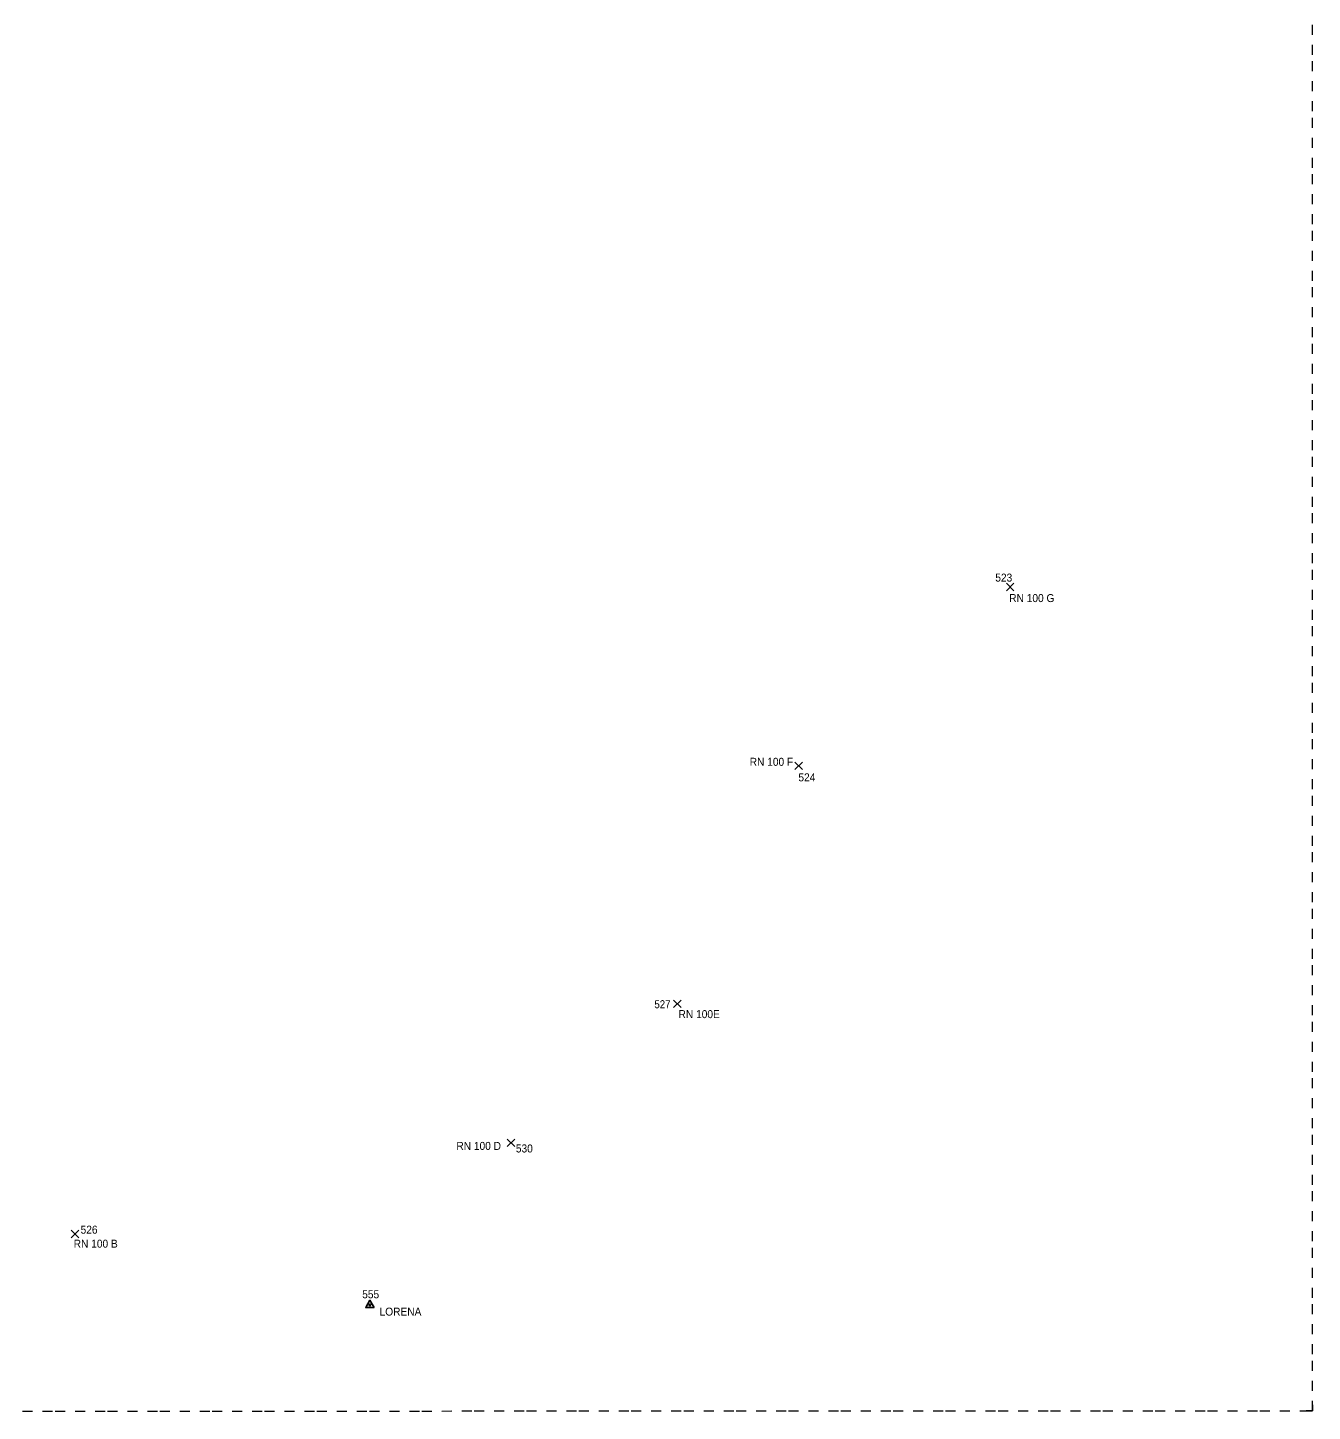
# Model space of a CAD drawing. Extents: x 474.3 to 500, y 7484.1 to 7511.8.
# Drawn here: x 487.15 to 500, y 7484.12 to 7497.95 of the extents above; entities that cross this region are included whole.
import ezdxf
from ezdxf.enums import TextEntityAlignment as Align

# ---------------------------------------------------------------- set-up
doc = ezdxf.new("R2010")
doc.units = 0
doc.header["$LTSCALE"] = 0.032
doc.header["$PDMODE"] = 32
doc.header["$PDSIZE"] = 0.016
doc.linetypes.add('SHORT_DASHED', pattern=[2.7, 1.5, -1.2])
for name, color, linetype, lineweight in [('1', 7, 'SHORT_DASHED', 13), ('42', 7, 'Continuous', 25), ('46', 7, 'Continuous', 25), ('63', 7, 'Continuous', 25)]:
    doc.layers.add(name, color=color, linetype=linetype, lineweight=lineweight)
doc.layers.add('61', color=7, linetype='Continuous')

msp = doc.modelspace()

# ---------------------------------------------------------------- linework, layer by layer
at = {"layer": '1'}
for points in [[(500, 7484.1219), (500, 7484.6867), (500, 7485.2515), (500, 7485.8162), (500, 7486.381), (500, 7486.9458), (500, 7487.5106), (500, 7488.0754), (500, 7488.6402), (500, 7489.2049), (500, 7489.7697), (500, 7490.3345), (500, 7490.8993), (500, 7491.4641), (500, 7492.0289), (500, 7492.5936), (500, 7493.1584), (500, 7493.7232), (500, 7494.288), (500, 7494.8528), (500, 7495.4175), (500, 7495.9823), (500, 7496.5471), (500, 7497.1119), (500, 7497.6767), (500, 7498.2414)], [(486.9038, 7484.1162), (487.4277, 7484.1167), (487.9515, 7484.1171), (488.4754, 7484.1175), (488.9992, 7484.1179), (489.5231, 7484.1183), (490.0469, 7484.1186), (490.5707, 7484.119), (491.0946, 7484.1193), (491.6184, 7484.1196), (492.1423, 7484.1199), (492.6661, 7484.1201), (493.19, 7484.1204), (493.7138, 7484.1206), (494.2377, 7484.1208), (494.7615, 7484.121), (495.2853, 7484.1212), (495.8092, 7484.1213), (496.333, 7484.1214), (496.8569, 7484.1216), (497.3807, 7484.1217), (497.9046, 7484.1217), (498.4284, 7484.1218), (498.9523, 7484.1219), (499.4761, 7484.1219), (500, 7484.1219)]]:
    msp.add_lwpolyline(points, dxfattribs=at)
at = {"layer": '42'}
for p, q in [((496.9411, 7492.394), (497.0161, 7492.319)), ((497.0161, 7492.394), (496.9411, 7492.319)), ((494.8268, 7490.607), (494.9018, 7490.532)), ((494.9018, 7490.607), (494.8268, 7490.532)), ((493.6134, 7488.2272), (493.6884, 7488.1522)), ((493.6884, 7488.2272), (493.6134, 7488.1522)), ((491.9499, 7486.8378), (492.0249, 7486.7628)), ((492.0249, 7486.8378), (491.9499, 7486.7628)), ((487.5897, 7485.9272), (487.6647, 7485.8522)), ((487.6647, 7485.9272), (487.5897, 7485.8522))]:
    msp.add_line(p, q, dxfattribs=at)
at = {"layer": '46'}
msp.add_lwpolyline([(490.6177, 7485.1541), (490.576, 7485.2265), (490.5341, 7485.1541)], close=True, dxfattribs=at)
msp.add_point((490.5759, 7485.1783), dxfattribs=at)
at = {"layer": '63'}
msp.add_lwpolyline([(499.9384, 7484.1219), (500, 7484.1219), (500, 7484.1826)], dxfattribs=at)

# ---------------------------------------------------------------- texts
at = {"layer": '61', "width": 0.95}
for s, p in [('523', (496.8298, 7492.4108)), ('RN 100 G', (496.969, 7492.206)), ('524', (494.8607, 7490.4137)), ('RN 100E', (493.6625, 7488.0468)), ('530', (492.0356, 7486.704)), ('526', (487.6832, 7485.8922)), ('RN 100 B', (487.6142, 7485.752)), ('555', (490.4991, 7485.2463)), ('LORENA', (490.6729, 7485.0726))]:
    msp.add_text(s, height=0.08, dxfattribs=at).set_placement(p)
at = {"layer": '61'}
for s, width, p in [('RN 100 F', 0.95, (494.8089, 7490.5694)), ('527', 0.9, (493.5818, 7488.1459)), ('RN 100 D', 0.95, (491.887, 7486.7294))]:
    msp.add_text(s, height=0.08, dxfattribs=dict(at, width=width)).set_placement(p, align=Align.RIGHT)

doc.saveas('drawing.dxf')
